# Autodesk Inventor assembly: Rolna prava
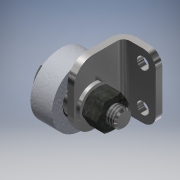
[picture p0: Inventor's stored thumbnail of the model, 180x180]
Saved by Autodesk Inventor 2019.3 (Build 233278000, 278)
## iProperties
Created: 2019-02
Part Number: Rolna prava
Material: Všeobecné
Document SubType Name: Assembly
Designer: B-hon
Author: B-hon
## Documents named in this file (5)
- C:\Users\B-hon\OneDrive\Plocha\Bakalářka2\Rolna prava.iam
- C:\Users\B-hon\OneDrive\Plocha\Bakalářka\Rolna.iam
- C:\Users\B-hon\OneDrive\Documents\Inventor\Content Center Files\R2019\cs-CZ\DIN 125-1  A\DIN 125 - A 8,4.ipt
- C:\Users\B-hon\OneDrive\Documents\Inventor\Content Center Files\R2019\cs-CZ\CSN EN 24034\ISO 4034 - M8CSN EN.ipt
- C:\Users\B-hon\OneDrive\Plocha\Bakalářka2\Držák rolny.ipt
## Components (4 placed, 4 different names)
1. Rolna:2 [sub-assembly] — Proti sobě:9, Proti sobě:10, Proti sobě:11, Stejný směr:1
2. DIN 125-1 A A 8,4:2 — Proti sobě:9, Vložit:13
3. CSN EN 24034 M8:2 — Vložit:13
4. Držák rolny:1 — Proti sobě:10, Proti sobě:11, Stejný směr:1
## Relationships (5: Mate 3, Insert 1, Flush 1)
- Proti sobě:9 [Mate]: Rolna:2 ↔ DIN 125-1 A A 8,4:2
- Vložit:13 [Insert]: DIN 125-1 A A 8,4:2 ↔ CSN EN 24034 M8:2
- Proti sobě:10 [Mate]: Rolna:2 ↔ Držák rolny:1
- Proti sobě:11 [Mate]: Rolna:2 ↔ Držák rolny:1
- Stejný směr:1 [Flush]: Rolna:2 ↔ Držák rolny:1
